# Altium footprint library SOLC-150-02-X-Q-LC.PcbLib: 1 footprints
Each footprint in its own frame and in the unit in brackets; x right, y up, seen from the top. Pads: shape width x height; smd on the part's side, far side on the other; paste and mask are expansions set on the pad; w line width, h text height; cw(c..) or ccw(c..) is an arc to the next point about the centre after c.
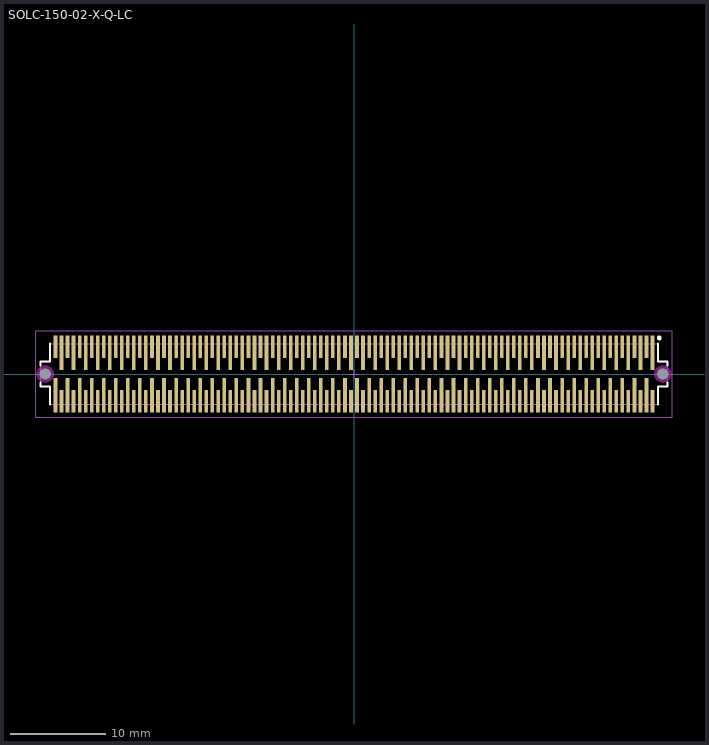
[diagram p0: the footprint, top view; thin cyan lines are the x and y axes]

## SOLC-150-02-X-Q-LC [mm] "1.27mm pitch, 200 pin, socket strip; 4 rows, w/locking clips, SMT"
height 4.62
pads (202):
  rect 0.38x2.36 smd mask+0: A1(30.797,2.885) A2(29.527,2.885) A3(28.258,2.885) A4(26.987,2.885) A5(25.717,2.885) A6(24.447,2.885) A7(23.177,2.885) A8(21.907,2.885) A9(20.637,2.885) A10(19.367,2.885) A11(18.098,2.885) A12(16.828,2.885) A13(15.557,2.885) A14(14.287,2.885) A15(13.018,2.885) A16(11.747,2.885) A17(10.477,2.885) A18(9.207,2.885) A19(7.938,2.885) A20(6.667,2.885) A21(5.397,2.885) A22(4.127,2.885) A23(2.857,2.885) A24(1.587,2.885) A25(0.318,2.885) A26(-0.953,2.885) A27(-2.222,2.885) A28(-3.492,2.885) A29(-4.763,2.885) A30(-6.032,2.885) A31(-7.302,2.885) A32(-8.572,2.885) A33(-9.842,2.885) A34(-11.112,2.885) A35(-12.383,2.885) A36(-13.652,2.885) A37(-14.922,2.885) A38(-16.192,2.885) A39(-17.462,2.885) A40(-18.732,2.885) A41(-20.002,2.885) A42(-21.273,2.885) A43(-22.543,2.885) A44(-23.812,2.885) A45(-25.082,2.885) A46(-26.352,2.885) A47(-27.622,2.885) A48(-28.892,2.885) A49(-30.162,2.885) A50(-31.432,2.885) D1(31.432,-2.885) D2(30.162,-2.885) D3(28.892,-2.885) D4(27.622,-2.885) D5(26.352,-2.885) D6(25.082,-2.885) D7(23.812,-2.885) D8(22.543,-2.885) D9(21.273,-2.885) D10(20.002,-2.885) D11(18.732,-2.885) D12(17.462,-2.885) D13(16.192,-2.885) D14(14.922,-2.885) D15(13.652,-2.885) D16(12.383,-2.885) D17(11.112,-2.885) D18(9.842,-2.885) D19(8.572,-2.885) D20(7.302,-2.885) D21(6.032,-2.885) D22(4.763,-2.885) D23(3.492,-2.885) D24(2.222,-2.885) D25(0.953,-2.885) D26(-0.318,-2.885) D27(-1.587,-2.885) D28(-2.857,-2.885) D29(-4.127,-2.885) D30(-5.397,-2.885) D31(-6.667,-2.885) D32(-7.938,-2.885) D33(-9.207,-2.885) D34(-10.477,-2.885) D35(-11.747,-2.885) D36(-13.018,-2.885) D37(-14.287,-2.885) D38(-15.557,-2.885) D39(-16.828,-2.885) D40(-18.098,-2.885) D41(-19.367,-2.885) D42(-20.637,-2.885) D43(-21.907,-2.885) D44(-23.177,-2.885) D45(-24.447,-2.885) D46(-25.717,-2.885) D47(-26.987,-2.885) D48(-28.258,-2.885) D49(-29.527,-2.885) D50(-30.797,-2.885)
  rect 0.38x3.63 smd mask+0: B1(31.432,2.25) B2(30.162,2.25) B3(28.892,2.25) B4(27.622,2.25) B5(26.352,2.25) B6(25.082,2.25) B7(23.812,2.25) B8(22.543,2.25) B9(21.273,2.25) B10(20.002,2.25) B11(18.732,2.25) B12(17.462,2.25) B13(16.192,2.25) B14(14.922,2.25) B15(13.652,2.25) B16(12.383,2.25) B17(11.112,2.25) B18(9.842,2.25) B19(8.572,2.25) B20(7.302,2.25) B21(6.032,2.25) B22(4.763,2.25) B23(3.492,2.25) B24(2.222,2.25) B25(0.953,2.25) B26(-0.318,2.25) B27(-1.587,2.25) B28(-2.857,2.25) B29(-4.127,2.25) B30(-5.397,2.25) B31(-6.667,2.25) B32(-7.938,2.25) B33(-9.207,2.25) B34(-10.477,2.25) B35(-11.747,2.25) B36(-13.018,2.25) B37(-14.287,2.25) B38(-15.557,2.25) B39(-16.828,2.25) B40(-18.098,2.25) B41(-19.367,2.25) B42(-20.637,2.25) B43(-21.907,2.25) B44(-23.177,2.25) B45(-24.447,2.25) B46(-25.717,2.25) B47(-26.987,2.25) B48(-28.258,2.25) B49(-29.527,2.25) B50(-30.797,2.25) C1(30.797,-2.25) C2(29.527,-2.25) C3(28.258,-2.25) C4(26.987,-2.25) C5(25.717,-2.25) C6(24.447,-2.25) C7(23.177,-2.25) C8(21.907,-2.25) C9(20.637,-2.25) C10(19.367,-2.25) C11(18.098,-2.25) C12(16.828,-2.25) C13(15.557,-2.25) C14(14.287,-2.25) C15(13.018,-2.25) C16(11.747,-2.25) C17(10.477,-2.25) C18(9.207,-2.25) C19(7.938,-2.25) C20(6.667,-2.25) C21(5.397,-2.25) C22(4.127,-2.25) C23(2.857,-2.25) C24(1.587,-2.25) C25(0.318,-2.25) C26(-0.953,-2.25) C27(-2.222,-2.25) C28(-3.492,-2.25) C29(-4.763,-2.25) C30(-6.032,-2.25) C31(-7.302,-2.25) C32(-8.572,-2.25) C33(-9.842,-2.25) C34(-11.112,-2.25) C35(-12.383,-2.25) C36(-13.652,-2.25) C37(-14.922,-2.25) C38(-16.192,-2.25) C39(-17.462,-2.25) C40(-18.732,-2.25) C41(-20.002,-2.25) C42(-21.273,-2.25) C43(-22.543,-2.25) C44(-23.812,-2.25) C45(-25.082,-2.25) C46(-26.352,-2.25) C47(-27.622,-2.25) C48(-28.892,-2.25) C49(-30.162,-2.25) C50(-31.432,-2.25)
  round 1 hole 1.2 unplated mask+0: MTG1(-32.512,0) MTG2(32.512,0)
Top Overlay:
  circle w0.25: c32.15,3.8 r0.125
  lines w0.2: -33,-0.9 -33,-1.3 -32,-1.3 -32,-3.2 ; -33,0.9 -33,1.3 -32,1.3 -32,3.2 ; 32,-3.2 32,-1.3 33,-1.3 33,-0.9 ; 32,3.2 32,1.3 33,1.3 33,0.9
Keep-Out Layer:
  pour cut-out: -31.604,0 -31.635,0.235 -31.726,0.454 -31.87,0.642 -32.058,0.786 -32.277,0.877 -32.512,0.908 -32.747,0.877 -32.966,0.786 -33.154,0.642 -33.298,0.454 -33.389,0.235 -33.42,0 -33.389,-0.235 -33.298,-0.454 -33.154,-0.642 -32.966,-0.786 -32.747,-0.877 -32.512,-0.908 -32.277,-0.877 -32.058,-0.786 -31.87,-0.642 -31.726,-0.454 -31.635,-0.235
  pour cut-out: 33.42,0 33.389,0.235 33.298,0.454 33.154,0.642 32.966,0.786 32.747,0.877 32.512,0.908 32.277,0.877 32.058,0.786 31.87,0.642 31.726,0.454 31.635,0.235 31.604,0 31.635,-0.235 31.726,-0.454 31.87,-0.642 32.058,-0.786 32.277,-0.877 32.512,-0.908 32.747,-0.877 32.966,-0.786 33.154,-0.642 33.298,-0.454 33.389,-0.235
Mechanical 12:
  lines w0.001: -33,-1.3 -32,-1.3 -32,-3.2 32,-3.2 32,-1.3 33,-1.3 33,1.3 32,1.3 32,3.2 -32,3.2 -32,1.3 -33,1.3 -33,-1.3
Mechanical 13:
  lines w0.1: -33,-1.3 -32,-1.3 -32,-3.2 32,-3.2 32,-1.3 33,-1.3 33,1.3 32,1.3 32,3.2 -32,3.2 -32,1.3 -33,1.3 -33,-1.3
  text ".Designator" at 0.127,-0.127 h1.52
Mechanical 15:
  lines w0.05: -0.5,0 0.5,0 ; 0,-0.5 0,0.5 ; -33.5,-4.55 33.5,-4.55 33.5,4.55 -33.5,4.55 -33.5,-4.55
